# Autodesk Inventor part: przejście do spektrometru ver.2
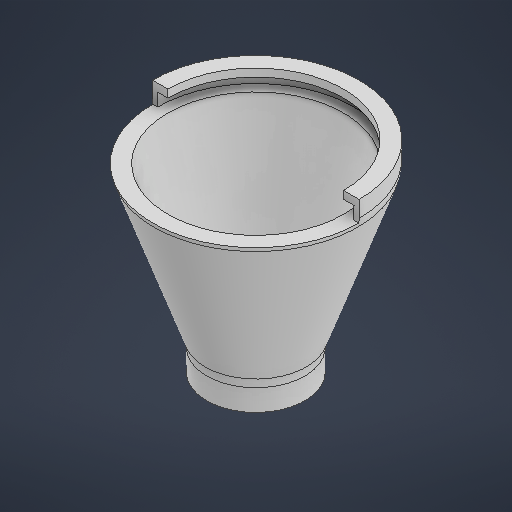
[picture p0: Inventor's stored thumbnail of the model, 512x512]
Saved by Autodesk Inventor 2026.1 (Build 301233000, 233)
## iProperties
Created: 2026-07
Part Number: przejście do spektrometru ver.2
Material: Ogólny
Document SubType Name: Modeling
Designer: Dell
Density: 1 g/cm^3
Appearance: Domyślna
Author: Dell
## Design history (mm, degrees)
sketch "Szkic1"
  geometry: C1 r 8 at (0, 0); C2 r 9.5 at (0, 0); 1 further point
  constraints: 2 centre point, 1 coincident
  dimensions: "d0" = 16 diameter of C1; "d1" = 1.5 radial gap between concentric circles of C1 C2
extrude "Wyciągnięcie proste1" new body sketch "Szkic1" distance "d2" = 5; taper "d3" = 0 deg
sketch "Szkic2"
  geometry: L1 (5, -9.5)-(5, 9.5) reference; L2 (5, 0)-(35, 0); L3 (35, 0)-(35, -17); L4 (35, -17)-(5, -8); L5 (35, -17)-(35, -18.5); L6 (35, -18.5)-(5, -9.5); L7 (35, 0)-(35, -18.5); L8 (35, -18.5)-(37, -18.5); L9 (37, -18.5)-(37, -20); L10 (37, -20)-(35, -20); L11 (35, -20)-(35, -18.5); L12 (35, -20)-(5, -9.5); L13 (37, -18.5)-(37, -17); L14 (37, -17)-(39, -17); L15 (39, -17)-(39, -20); L16 (39, -20)-(37, -20); 1 further point
  constraints: 30 end point, 8 perpendicular, 2 point on line, 2 vertical, 1 collinear, 1 horizontal, 1 midpoint
  dimensions: "d4" = 30 distance of L2.start L2.end; "d5" = 17 distance of L2.end L3.end; "d6" = 1.5 distance of L3.end L5.end; "d7" = 18.5 distance of L2.end L5.end (derived); "d8" = 2 distance of L5.end L8.end; "d9" = 1.5 distance of L8.end L9.end
revolve "Obrót1" sketch "Szkic2" stored, may be unused: angle "d10" = 90 deg
fillet "Zaokrąglenie1" dims "d11" = 5
sketch "Szkic3"
  geometry: L1 (21, 0)-(-24, 0); L2 (-24, 0)-(-24, -23); L3 (-24, -23)-(21, -23); L4 (21, -23)-(21, 0); 1 further point
  constraints: 8 end point, 2 parallel, 1 horizontal, 1 perpendicular
extrude "Wyciągnięcie proste2" cut sketch "Szkic3" distance "d12" = 4; taper "d13" = 0 deg
sketch "Szkic4"
  geometry: C1 r 19 at (0, 0); A1 r 18.5 centre (0, 0) between (18.5, 0) and (-18.5, 0) reference; 1 further point
  constraints: 1 centre point, 1 coincident, 1 horizontal alignment, 2 other
  dimensions: "d14" = 0.5 dimension on C1
extrude "Wyciągnięcie proste3" cut sketch "Szkic4" distance "d15" = 2.5; taper "d16" = 0 deg
node "Bryła1"
